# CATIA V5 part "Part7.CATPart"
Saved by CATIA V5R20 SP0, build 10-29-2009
Part number: 9CS101615
Revision: ANY
Definition: UNKNOWN
Nomenclature: 9CS101615
Source: Unknown
Bounding box of the stored display mesh (mm): x -8 to 8, y -7.5 to 7.5, z -8 to 8
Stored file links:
  C:\Users\Utente\Desktop\IO LAVORO\3D X SITO CF\CUMSA\3D files PW\pw101630\pw101630_injection\Part7.CATPart
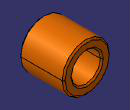
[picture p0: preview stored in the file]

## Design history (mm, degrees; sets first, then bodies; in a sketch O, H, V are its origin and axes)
Body1 "Revolución1" (main body)
  Solid1: solid without history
